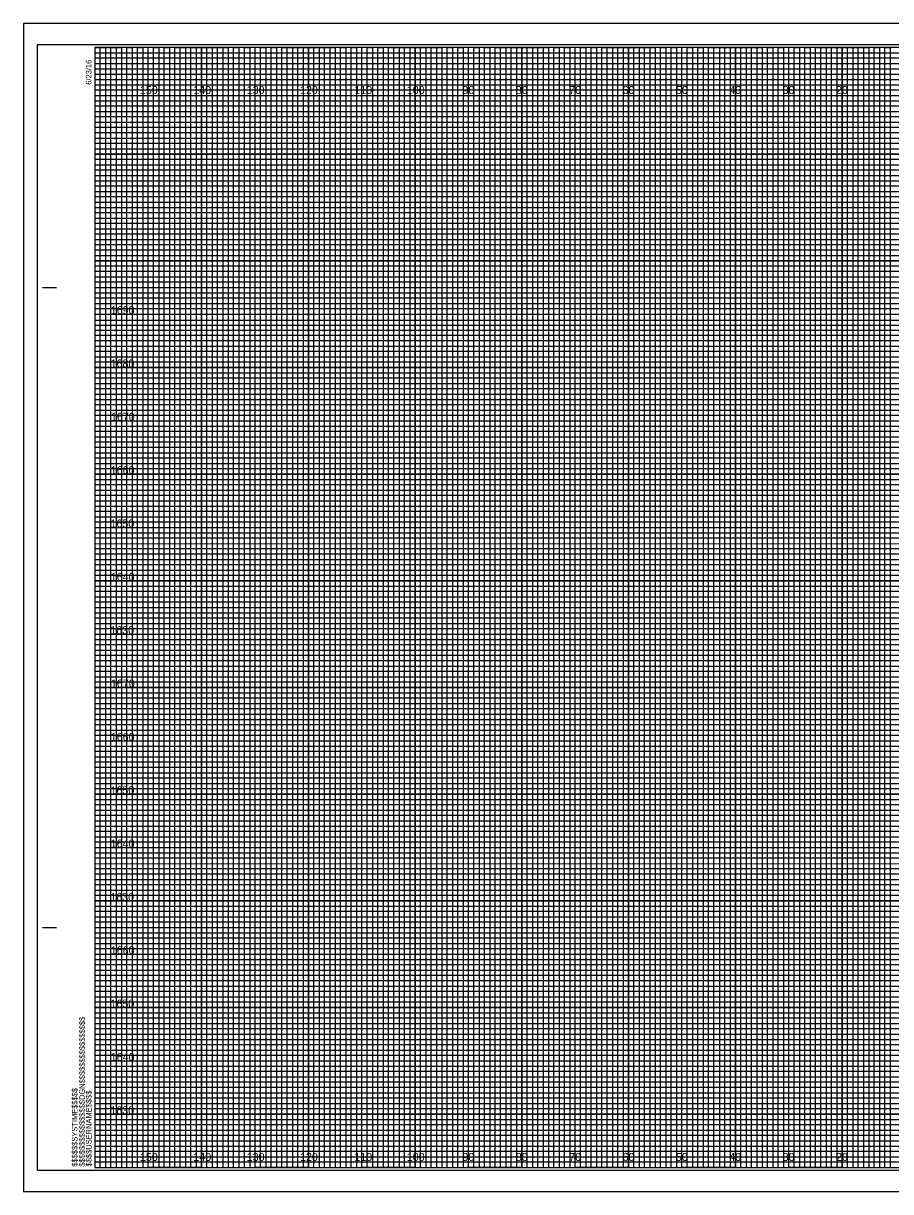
# Model space of a CAD drawing. Extents: x -13 to 1780, y -15 to 3284.
# Drawn here: x 365.9 to 528.4, y -6.6 to 212.4 of the extents above; entities that cross this region are included whole.
import ezdxf

# ---------------------------------------------------------------- set-up
doc = ezdxf.new("R2010")
doc.units = 0
for name, color, linetype in [('Prop Retaining Wall', 7, 'Continuous'), ('Prop SS Cut Line', 7, 'Continuous'), ('Prop SS Fill Line', 7, 'Continuous'), ('Prop SS Transition Line', 7, 'Continuous'), ('Prop XS Earthwork Shape', 7, 'Continuous'), ('Prop XS Noise Wall', 7, 'Continuous'), ('Prop XS Station Labels', 7, 'Continuous'), ('Raster_Level_0', 7, 'Continuous'), ('Scratch_Level_3', 7, 'Continuous'), ('Scratch_Level_7', 7, 'Continuous'), ('Typical Bridge Rail CELL', 7, 'Continuous')]:
    doc.layers.add(name, color=color, linetype=linetype)

msp = doc.modelspace()

# ---------------------------------------------------------------- linework, layer by layer
at = {"layer": 'Prop Retaining Wall'}
for p, q in [((369.46, 162.94), (371.96, 162.94)), ((369.56, 162.94), (372.06, 162.94)), ((369.46, 42.94), (371.96, 42.94)), ((369.56, 42.94), (372.06, 42.94)), ((379.26, -2.06), (379.26, -2.06)), ((379.26, -2.06), (379.26, -2.06)), ((379.26, -2.06), (379.26, -2.06)), ((379.26, -2.06), (379.26, -2.06)), ((379.26, -2.06), (379.26, -2.06)), ((379.26, -2.06), (379.26, -2.06)), ((379.26, -2.06), (379.26, -2.06))]:
    msp.add_line(p, q, dxfattribs=at)
msp.add_lwpolyline([(699.26, 207.94), (379.26, 207.94), (379.26, -2.06), (699.26, -2.06)], close=True, dxfattribs=at)
at = {"layer": 'Prop SS Cut Line'}
for points in [[(379.26, 207.94), (384.26, 207.94), (384.26, -2.06), (394.26, -2.06), (394.26, 207.94), (404.26, 207.94), (404.26, -2.06), (414.26, -2.06), (414.26, 207.94), (424.26, 207.94), (424.26, -2.06), (434.26, -2.06), (434.26, 207.94), (444.26, 207.94), (444.26, -2.06), (454.26, -2.06), (454.26, 207.94), (464.26, 207.94), (464.26, -2.06), (474.26, -2.06), (474.26, 207.94), (484.26, 207.94), (484.26, -2.06), (494.26, -2.06), (494.26, 207.94), (504.26, 207.94), (504.26, -2.06), (514.26, -2.06), (514.26, 207.94), (524.26, 207.94), (524.26, -2.06), (534.26, -2.06)], [(379.26, 202.94), (654.26, 202.94)], [(379.26, 182.94), (699.26, 182.94), (699.26, 192.94), (379.26, 192.94)], [(379.26, 162.94), (699.26, 162.94), (699.26, 172.94), (379.26, 172.94)], [(379.26, 142.94), (699.26, 142.94), (699.26, 152.94), (379.26, 152.94)], [(379.26, 122.94), (699.26, 122.94), (699.26, 132.94), (379.26, 132.94)], [(379.26, 102.94), (699.26, 102.94), (699.26, 112.94), (379.26, 112.94)], [(379.26, 82.94), (699.26, 82.94), (699.26, 92.94), (379.26, 92.94)], [(379.26, 62.94), (699.26, 62.94), (699.26, 72.94), (379.26, 72.94)], [(379.26, 42.94), (699.26, 42.94), (699.26, 52.94), (379.26, 52.94)], [(379.26, 22.94), (699.26, 22.94), (699.26, 32.94), (379.26, 32.94)], [(379.26, 2.94), (699.26, 2.94), (699.26, 12.94), (379.26, 12.94)]]:
    msp.add_lwpolyline(points, dxfattribs=at)
at = {"layer": 'Prop SS Fill Line'}
for p, q in [((389.26, 207.94), (379.26, 207.94)), ((389.26, -2.06), (389.26, 207.94)), ((409.26, 207.94), (399.26, 207.94)), ((399.26, 207.94), (399.26, -2.06)), ((409.26, -2.06), (409.26, 207.94)), ((429.26, 207.94), (419.26, 207.94)), ((419.26, 207.94), (419.26, -2.06)), ((429.26, -2.06), (429.26, 207.94)), ((449.26, 207.94), (439.26, 207.94)), ((439.26, 207.94), (439.26, -2.06)), ((449.26, -2.06), (449.26, 207.94)), ((469.26, 207.94), (459.26, 207.94)), ((459.26, 207.94), (459.26, -2.06)), ((469.26, -2.06), (469.26, 207.94)), ((489.26, 207.94), (479.26, 207.94)), ((479.26, 207.94), (479.26, -2.06)), ((489.26, -2.06), (489.26, 207.94)), ((509.26, 207.94), (499.26, 207.94)), ((499.26, 207.94), (499.26, -2.06)), ((509.26, -2.06), (509.26, 207.94)), ((529.26, 207.94), (519.26, 207.94)), ((519.26, 207.94), (519.26, -2.06)), ((399.26, -2.06), (389.26, -2.06)), ((419.26, -2.06), (409.26, -2.06)), ((439.26, -2.06), (429.26, -2.06)), ((459.26, -2.06), (449.26, -2.06)), ((479.26, -2.06), (469.26, -2.06)), ((499.26, -2.06), (489.26, -2.06)), ((519.26, -2.06), (509.26, -2.06))]:
    msp.add_line(p, q, dxfattribs=at)
for points in [[(379.26, 197.94), (699.26, 197.94), (699.26, 187.94), (379.26, 187.94)], [(379.26, 177.94), (699.26, 177.94), (699.26, 167.94), (379.26, 167.94)], [(379.26, 157.94), (699.26, 157.94), (699.26, 147.94), (379.26, 147.94)], [(379.26, 137.94), (699.26, 137.94), (699.26, 127.94), (379.26, 127.94)], [(379.26, 117.94), (699.26, 117.94), (699.26, 107.94), (379.26, 107.94)], [(379.26, 97.94), (699.26, 97.94), (699.26, 87.94), (379.26, 87.94)], [(379.26, 77.94), (699.26, 77.94), (699.26, 67.94), (379.26, 67.94)], [(379.26, 57.94), (699.26, 57.94), (699.26, 47.94), (379.26, 47.94)], [(379.26, 37.94), (699.26, 37.94), (699.26, 27.94), (379.26, 27.94)], [(379.26, 17.94), (699.26, 17.94), (699.26, 7.94), (379.26, 7.94)]]:
    msp.add_lwpolyline(points, dxfattribs=at)
at = {"layer": 'Prop SS Transition Line'}
for p, q in [((379.26, 206.94), (639.26, 206.94)), ((639.26, 205.92), (379.26, 205.92)), ((379.26, 205.92), (379.26, 204.94)), ((379.26, 204.94), (639.26, 204.94)), ((639.26, 203.83), (379.26, 203.83)), ((379.26, 203.83), (379.26, 201.94)), ((379.26, 201.94), (699.26, 201.94))]:
    msp.add_line(p, q, dxfattribs=at)
for points in [[(379.26, 200.94), (649.26, 200.94), (699.26, 200.94), (699.26, 199.94), (379.26, 199.94)], [(379.26, 198.94), (699.26, 198.94), (699.26, 196.94), (379.26, 196.94)], [(379.26, 195.94), (699.26, 195.94), (699.26, 194.94), (379.26, 194.92)], [(379.26, 193.94), (699.26, 193.94), (699.26, 191.94), (379.26, 191.94)], [(379.26, 190.94), (699.26, 190.94), (699.26, 189.94), (379.26, 189.94)], [(379.26, 188.94), (699.26, 188.94), (699.26, 186.94), (379.26, 186.94)], [(379.26, 185.94), (699.26, 185.94), (699.26, 184.94), (379.26, 184.94)], [(379.26, 183.94), (699.26, 183.94), (699.26, 181.94), (379.26, 181.94)], [(379.26, 180.94), (699.26, 180.94), (699.26, 179.94), (379.26, 179.94)], [(379.26, 178.94), (699.26, 178.94), (699.26, 176.94), (379.26, 176.94)], [(379.26, 175.94), (699.26, 175.94), (699.26, 174.94), (379.26, 174.94)], [(379.26, 173.94), (699.26, 173.94), (699.26, 171.89), (699.26, 170.94), (699.26, 169.94), (379.26, 169.94)], [(379.26, 171.94), (699.26, 171.94), (699.26, 170.94), (379.26, 170.94)], [(379.26, 168.94), (699.26, 168.94), (699.26, 166.94), (379.26, 166.97)], [(379.26, 166.97), (699.26, 166.94), (699.26, 165.94), (379.26, 165.94)], [(379.26, 164.94), (699.26, 164.94), (699.26, 163.94), (379.26, 163.94)], [(379.26, 161.94), (699.26, 161.94), (699.26, 160.94), (379.26, 160.94)], [(379.26, 159.94), (699.26, 159.94), (699.26, 158.94), (379.26, 158.94)], [(379.19, 156.83), (699.26, 156.83), (699.26, 155.82), (379.19, 155.82)], [(379.26, 154.94), (699.26, 154.94), (699.26, 153.94), (379.26, 153.94)], [(379.26, 151.94), (699.26, 151.94), (699.26, 150.94), (379.26, 150.94)], [(379.26, 149.94), (699.26, 149.94), (699.26, 148.94), (379.26, 148.94)], [(379.26, 146.94), (699.26, 146.94), (699.26, 145.94), (379.26, 145.94)], [(379.26, 144.94), (699.26, 144.94), (699.26, 143.94), (379.26, 143.94)], [(379.26, 141.94), (699.26, 141.94), (699.26, 140.94), (379.26, 140.94)], [(379.26, 139.94), (699.26, 139.94), (699.26, 138.94), (379.26, 138.94)], [(379.26, 136.94), (699.26, 136.94), (699.25, 135.92), (379.26, 135.94)], [(379.26, 134.94), (699.26, 134.94), (699.26, 133.94), (379.26, 133.94)], [(379.26, 131.94), (699.26, 131.94), (699.26, 130.94), (379.26, 130.94)], [(379.26, 129.94), (699.26, 129.94), (699.26, 128.94), (379.26, 128.94)], [(379.26, 126.94), (699.26, 126.94), (699.26, 125.94), (379.26, 125.94)], [(379.26, 124.94), (699.26, 124.94), (699.26, 123.94), (379.26, 123.94)], [(379.26, 121.94), (699.26, 121.94), (699.26, 120.94), (379.26, 120.94)], [(379.26, 119.94), (699.26, 119.94), (699.26, 118.94), (379.26, 118.94)], [(379.26, 116.94), (699.26, 116.94), (699.26, 115.94), (379.26, 115.94)], [(379.26, 114.93), (699.33, 114.85), (699.26, 113.94), (379.26, 113.94)], [(379.26, 111.94), (699.26, 111.94), (699.26, 110.94), (379.26, 110.94)], [(379.26, 109.94), (699.26, 109.94), (699.26, 108.94), (379.26, 108.94)], [(379.26, 106.94), (699.26, 106.94), (699.26, 105.94), (379.26, 105.94)], [(379.26, 104.94), (699.26, 104.94), (699.26, 103.94), (379.26, 103.94)], [(379.26, 101.94), (699.26, 101.94), (699.26, 100.94), (379.26, 100.94)], [(379.26, 99.94), (699.26, 99.94), (699.26, 98.94), (379.26, 98.94)], [(379.26, 96.94), (699.26, 96.94), (699.26, 95.94), (379.26, 95.94)], [(379.26, 94.94), (699.26, 94.94), (699.26, 93.94), (379.26, 93.94)], [(379.26, 91.94), (699.26, 91.94), (699.26, 90.94), (379.26, 90.94)], [(379.26, 89.94), (699.26, 89.94), (699.26, 88.94), (379.26, 88.94)], [(379.26, 86.94), (699.26, 86.94), (699.26, 85.94), (379.26, 85.94)], [(379.26, 84.94), (699.26, 84.94), (699.26, 83.94), (379.26, 83.94)], [(379.26, 81.94), (699.26, 81.94), (699.26, 80.94), (379.26, 80.94)], [(379.26, 79.94), (699.26, 79.94), (699.26, 78.94), (379.26, 78.94)], [(379.26, 76.94), (699.26, 76.94), (699.25, 75.92), (379.26, 75.94)], [(379.26, 74.94), (699.26, 74.94), (699.26, 73.94), (379.26, 73.94)], [(379.26, 71.94), (699.26, 71.94), (699.26, 70.94), (379.26, 70.94)], [(379.26, 69.94), (699.26, 69.94), (699.26, 68.94), (379.26, 68.94)], [(379.26, 66.94), (699.26, 66.94), (699.26, 65.94), (379.26, 65.94)], [(379.26, 64.94), (699.26, 64.94), (699.26, 63.94), (379.26, 63.94)], [(379.26, 61.94), (699.26, 61.94), (699.26, 60.94), (379.26, 60.94)], [(379.26, 59.94), (699.26, 59.94), (699.26, 58.94), (379.26, 58.94)], [(379.26, 56.94), (699.26, 56.94), (699.26, 55.94), (379.26, 55.94)], [(379.26, 54.93), (699.33, 54.85), (699.26, 53.94), (379.26, 53.94)], [(379.26, 51.94), (699.26, 51.94), (699.26, 50.94), (379.26, 50.94)], [(379.26, 49.94), (699.26, 49.94), (699.26, 48.94), (379.26, 48.94)], [(379.26, 46.94), (699.26, 46.94), (699.26, 45.94), (379.26, 45.94)], [(379.26, 44.94), (699.26, 44.94), (699.26, 43.94), (379.26, 43.94)], [(379.26, 41.94), (699.26, 41.94), (699.26, 40.94), (379.26, 40.94)], [(379.26, 39.94), (699.26, 39.94), (699.26, 38.94), (379.26, 38.94)], [(379.26, 36.94), (699.26, 36.94), (699.26, 35.94), (379.26, 35.94)], [(379.26, 34.94), (699.26, 34.94), (699.26, 33.94), (379.26, 33.94)], [(379.26, 31.94), (699.26, 31.94), (699.26, 30.94), (379.26, 30.94)], [(379.26, 29.94), (699.26, 29.94), (699.26, 28.94), (379.26, 28.94)], [(379.26, 26.94), (699.26, 26.94), (699.26, 25.94), (379.26, 25.94)], [(379.26, 24.94), (699.26, 24.94), (699.26, 23.94), (379.26, 23.94)], [(379.26, 21.94), (699.26, 21.94), (699.26, 20.94), (379.26, 20.94)], [(379.26, 19.94), (699.26, 19.94), (699.26, 18.94), (379.26, 18.94)], [(379.26, 16.94), (699.26, 16.94), (699.26, 15.94), (379.26, 15.94)], [(379.26, 14.94), (699.26, 14.94), (699.26, 13.94), (379.26, 13.94)], [(379.26, 11.94), (699.26, 11.94), (699.26, 10.94), (379.26, 10.94)], [(379.26, 9.94), (699.26, 9.94), (699.26, 8.94), (379.26, 8.94)], [(379.26, 6.94), (699.26, 6.94), (699.26, 5.94), (379.26, 5.94)], [(379.26, 4.94), (699.26, 4.94), (699.26, 3.94), (379.26, 3.94)], [(379.26, 1.94), (699.26, 1.94), (699.26, 0.94), (379.26, 0.94)], [(379.26, -0.06), (699.26, -0.06), (699.26, -1.06), (379.26, -1.06)]]:
    msp.add_lwpolyline(points, dxfattribs=at)
at = {"layer": 'Prop XS Earthwork Shape'}
msp.add_lwpolyline([(365.86, -6.56), (702.56, -6.56), (702.56, 212.44), (365.86, 212.44)], close=True, dxfattribs=at)
at = {"layer": 'Prop XS Noise Wall'}
for p, q in [((389.26, -2.06), (389.26, 207.94)), ((399.26, -2.06), (399.26, 207.94)), ((409.26, -2.06), (409.26, 207.94)), ((419.26, -2.06), (419.26, 207.94)), ((429.26, -2.06), (429.26, 207.94)), ((439.26, -2.06), (439.26, 207.94)), ((449.26, -2.06), (449.26, 207.94)), ((459.26, -2.06), (459.26, 207.94)), ((469.26, -2.06), (469.26, 207.94)), ((479.26, -2.06), (479.26, 207.94)), ((489.26, -2.06), (489.26, 207.94)), ((499.26, -2.06), (499.26, 207.94)), ((509.26, -2.06), (509.26, 207.94)), ((519.26, -2.06), (519.26, 207.94)), ((379.26, 197.94), (699.26, 197.94)), ((379.26, 187.94), (699.26, 187.94)), ((379.26, 177.94), (699.26, 177.94)), ((379.26, 167.94), (699.26, 167.94)), ((379.26, 157.94), (699.26, 157.94)), ((379.26, 147.94), (699.26, 147.94)), ((379.26, 137.94), (699.26, 137.94)), ((379.26, 127.94), (699.26, 127.94)), ((379.26, 117.94), (699.26, 117.94)), ((379.26, 107.94), (699.26, 107.94)), ((379.26, 97.94), (699.26, 97.94)), ((379.26, 87.94), (699.26, 87.94)), ((379.26, 77.94), (699.26, 77.94)), ((379.26, 67.94), (699.26, 67.94)), ((379.26, 57.94), (699.26, 57.94)), ((379.26, 47.94), (699.26, 47.94)), ((379.26, 37.94), (699.26, 37.94)), ((379.26, 27.94), (699.26, 27.94)), ((379.26, 17.94), (699.26, 17.94)), ((379.26, 7.94), (699.26, 7.94))]:
    msp.add_line(p, q, dxfattribs=at)
at = {"layer": 'Prop XS Station Labels'}
for p, q in [((702.56, 212.44), (365.86, 212.44)), ((365.86, 212.44), (365.86, -6.56)), ((365.86, -6.56), (702.56, -6.56))]:
    msp.add_line(p, q, dxfattribs=at)
at = {"layer": 'Scratch_Level_7'}
msp.add_lwpolyline([(368.46, -2.56), (701.66, -2.56), (701.66, 208.44), (368.46, 208.44)], close=True, dxfattribs=at)
at = {"layer": 'Typical Bridge Rail CELL'}
for points in [[(379.26, -2.06), (380.26, -2.06), (380.26, 207.94), (381.26, 207.94), (381.26, -2.06)], [(381.26, -2.06), (382.26, -2.06), (382.26, 207.94), (383.26, 207.94), (383.26, -2.06)], [(384.26, -2.06), (385.26, -2.06), (385.26, 207.94), (386.26, 207.94), (386.26, -2.06)], [(386.26, -2.06), (387.26, -2.06), (387.26, 207.94), (388.26, 207.94), (388.26, -2.06)], [(389.26, -2.06), (390.26, -2.06), (390.26, 207.94), (391.26, 207.94), (391.26, -2.06)], [(391.26, -2.06), (392.26, -2.06), (392.26, 207.94), (393.26, 207.94), (393.26, -2.06)], [(394.26, -2.06), (395.26, -2.06), (395.26, 207.94), (396.26, 207.94), (396.26, -2.06)], [(396.26, -2.06), (397.26, -2.06), (397.26, 207.94), (398.26, 207.94), (398.26, -2.06)], [(399.26, -2.06), (400.26, -2.06), (400.26, 207.94), (401.26, 207.94), (401.26, -2.06)], [(401.26, -2.06), (402.26, -2.06), (402.26, 207.94), (403.26, 207.94), (403.26, -2.06)], [(404.26, -2.06), (405.26, -2.06), (405.26, 207.94), (406.26, 207.94), (406.26, -2.06)], [(406.26, -2.06), (407.26, -2.06), (407.26, 207.94), (408.26, 207.94), (408.26, -2.06)], [(409.26, -2.06), (410.26, -2.06), (410.26, 207.94), (411.26, 207.94), (411.26, -2.06)], [(411.26, -2.06), (412.26, -2.06), (412.26, 207.94), (413.26, 207.94), (413.26, -2.06)], [(414.26, -2.06), (415.26, -2.06), (415.26, 207.94), (416.26, 207.94), (416.26, -2.06)], [(416.26, -2.06), (417.26, -2.06), (417.26, 207.94), (418.26, 207.94), (418.26, -2.06)], [(419.26, -2.06), (420.26, -2.06), (420.26, 207.94), (421.26, 207.94), (421.26, -2.06)], [(421.26, -2.06), (422.26, -2.06), (422.26, 207.94), (423.26, 207.94), (423.26, -2.06)], [(424.26, -2.06), (425.26, -2.06), (425.26, 207.94), (426.26, 207.94), (426.26, -2.06)], [(426.26, -2.06), (427.26, -2.06), (427.26, 207.94), (428.26, 207.94), (428.26, -2.06)], [(429.26, -2.06), (430.26, -2.06), (430.26, 207.94), (431.26, 207.94), (431.26, -2.06)], [(431.26, -2.06), (432.26, -2.06), (432.26, 207.94), (433.26, 207.94), (433.26, -2.06)], [(434.26, -2.06), (435.26, -2.06), (435.26, 207.94), (436.26, 207.94), (436.26, -2.06)], [(436.26, -2.06), (437.26, -2.06), (437.26, 207.94), (438.26, 207.94), (438.26, -2.06)], [(439.26, -2.06), (440.26, -2.06), (440.26, 207.94), (441.26, 207.94), (441.26, -2.06)], [(441.26, -2.06), (442.26, -2.06), (442.26, 207.94), (443.26, 207.94), (443.26, -2.06)], [(444.26, -2.06), (445.26, -2.06), (445.26, 207.94), (446.26, 207.94), (446.26, -2.06)], [(446.26, -2.06), (447.26, -2.06), (447.26, 207.94), (448.26, 207.94), (448.26, -2.06)], [(449.26, -2.06), (450.26, -2.06), (450.26, 207.94), (451.26, 207.94), (451.26, -2.06)], [(451.26, -2.06), (452.26, -2.06), (452.26, 207.94), (453.26, 207.94), (453.26, -2.06)], [(454.26, -2.06), (455.26, -2.06), (455.26, 207.94), (456.26, 207.94), (456.26, -2.06)], [(456.26, -2.06), (457.26, -2.06), (457.26, 207.94), (458.26, 207.94), (458.26, -2.06)], [(459.26, -2.06), (460.26, -2.06), (460.26, 207.94), (461.26, 207.94), (461.26, -2.06)], [(461.26, -2.06), (462.26, -2.06), (462.26, 207.94), (463.26, 207.94), (463.26, -2.06)], [(464.26, -2.06), (465.26, -2.06), (465.26, 207.94), (466.26, 207.94), (466.26, -2.06)], [(466.26, -2.06), (467.26, -2.06), (467.26, 207.94), (468.26, 207.94), (468.26, -2.06)], [(469.26, -2.06), (470.26, -2.06), (470.26, 207.94), (471.26, 207.94), (471.26, -2.06)], [(471.26, -2.06), (472.26, -2.06), (472.26, 207.94), (473.26, 207.94), (473.26, -2.06)], [(474.26, -2.06), (475.26, -2.06), (475.26, 207.94), (476.26, 207.94), (476.26, -2.06)], [(476.26, -2.06), (477.26, -2.06), (477.26, 207.94), (478.26, 207.94), (478.26, -2.06)], [(479.26, -2.06), (480.26, -2.06), (480.26, 207.94), (481.26, 207.94), (481.26, -2.06)], [(481.26, -2.06), (482.26, -2.06), (482.26, 207.94), (483.26, 207.94), (483.26, -2.06)], [(484.26, -2.06), (485.26, -2.06), (485.26, 207.94), (486.26, 207.94), (486.26, -2.06)], [(486.26, -2.06), (487.26, -2.06), (487.26, 207.94), (488.26, 207.94), (488.26, -2.06)], [(489.26, -2.06), (490.26, -2.06), (490.26, 207.94), (491.26, 207.94), (491.26, -2.06)], [(491.26, -2.06), (492.26, -2.06), (492.26, 207.94), (493.26, 207.94), (493.26, -2.06)], [(494.26, -2.06), (495.26, -2.06), (495.26, 207.94), (496.26, 207.94), (496.26, -2.06)], [(496.26, -2.06), (497.26, -2.06), (497.26, 207.94), (498.26, 207.94), (498.26, -2.06)], [(499.26, -2.06), (500.26, -2.06), (500.26, 207.94), (501.26, 207.94), (501.26, -2.06)], [(501.26, -2.06), (502.26, -2.06), (502.26, 207.94), (503.26, 207.94), (503.26, -2.06)], [(504.26, -2.06), (505.26, -2.06), (505.26, 207.94), (506.26, 207.94), (506.26, -2.06)], [(506.26, -2.06), (507.26, -2.06), (507.26, 207.94), (508.26, 207.94), (508.26, -2.06)], [(509.26, -2.06), (510.26, -2.06), (510.26, 207.94), (511.26, 207.94), (511.26, -2.06)], [(511.26, -2.06), (512.26, -2.06), (512.26, 207.94), (513.26, 207.94), (513.26, -2.06)], [(514.26, -2.06), (515.26, -2.06), (515.26, 207.94), (516.26, 207.94), (516.26, -2.06)], [(516.26, -2.06), (517.26, -2.06), (517.26, 207.94), (518.26, 207.94), (518.26, -2.06)], [(519.26, -2.06), (520.26, -2.06), (520.26, 207.94), (521.26, 207.94), (521.26, -2.06)], [(521.26, -2.06), (522.26, -2.06), (522.26, 207.94), (523.26, 207.94), (523.26, -2.06)], [(524.26, -2.06), (525.26, -2.06), (525.26, 207.94), (526.26, 207.94), (526.26, -2.06)], [(526.26, -2.06), (527.26, -2.06), (527.26, 207.94), (528.26, 207.94), (528.26, -2.06)]]:
    msp.add_lwpolyline(points, dxfattribs=at)

# ---------------------------------------------------------------- texts
at = {"layer": 'Prop Retaining Wall'}
for s, p in [('6/23/16', (378.61, 200.94)), ('$$$$$$$$$$$$$$$$DGN$$$$$$$$$$$$$$$$', (377.38, -1.88)), ('$$$$$$SYSTIME$$$$$', (376, -1.88)), ('$$$$USERNAME$$$$', (378.64, -1.83))]:
    msp.add_text(s, height=1.05, rotation=90, dxfattribs=at).set_placement(p)
at = {"layer": 'Raster_Level_0'}
for s, p in [('150', (387.7, 199.19)), ('140', (397.7, 199.19)), ('130', (407.7, 199.19)), ('120', (417.7, 199.19)), ('110', (427.88, 199.19)), ('100', (437.7, 199.19)), ('90', (448.12, 199.19)), ('80', (458.12, 199.19)), ('70', (468.12, 199.19)), ('60', (478.12, 199.19)), ('50', (488.12, 199.19)), ('40', (498.12, 199.19)), ('30', (508.12, 199.19)), ('20', (518.12, 199.19)), ('150', (387.7, -0.81)), ('140', (397.7, -0.81)), ('130', (407.7, -0.81)), ('120', (417.7, -0.81)), ('110', (427.88, -0.81)), ('100', (437.7, -0.81)), ('90', (448.12, -0.81)), ('80', (458.12, -0.81)), ('70', (468.12, -0.81)), ('60', (478.12, -0.81)), ('50', (488.12, -0.81)), ('40', (498.12, -0.81)), ('30', (508.12, -0.81)), ('20', (518.12, -0.81))]:
    msp.add_text(s, height=1.5, dxfattribs=at).set_placement(p)
at = {"layer": 'Scratch_Level_3'}
for s, p in [('1690', (382.23, 157.94)), ('1680', (382.2, 147.94)), ('1670', (382.26, 137.94)), ('1660', (382.23, 127.94)), ('1650', (382.18, 117.94)), ('1640', (382.23, 107.94)), ('1630', (382.15, 97.94)), ('1670', (382.26, 87.94)), ('1660', (382.23, 77.94)), ('1650', (382.18, 67.94)), ('1640', (382.23, 57.94)), ('1630', (382.15, 47.94)), ('1660', (382.23, 37.94)), ('1650', (382.18, 27.94)), ('1640', (382.23, 17.94)), ('1630', (382.15, 7.94))]:
    msp.add_text(s, height=1.5, dxfattribs=at).set_placement(p)

doc.saveas('drawing.dxf')
